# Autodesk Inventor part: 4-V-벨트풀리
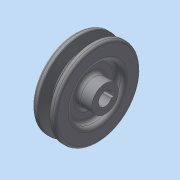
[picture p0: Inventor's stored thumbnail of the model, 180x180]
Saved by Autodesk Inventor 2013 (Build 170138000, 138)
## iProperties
Created: 2015-02
Part Number: 4-V-벨트풀리
Material: 일반
Document SubType Name: Modeling
Designer: Administrator
Density: 1 g/cm^3
Author: Administrator
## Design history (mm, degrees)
sketch "스케치1"
  geometry: L1 (0, 0)-(-25, 0); L2 (0, 11)-(0, 0); L3 (-6, 33.2)-(-6, 24.5); L4 (-12, 14)-(-12, 18.5); L5 (-9, 21.5)-(-9, 21.5); L6 (-22, 21.5)-(-22, 21.5); L7 (-19, 18.5)-(-19, 14); L8 (-22, 11)-(-25, 11); L9 (-25, 0)-(-25, 11); L10 (-25, 24.5)-(-25, 33.2); L11 (-20.217, 34.846)-(-17.79, 26.908); L12 (-16.834, 26.2)-(-14.166, 26.2); L13 (-13.21, 26.908)-(-10.783, 34.846); L14 (-23, 35.2)-(-20.695, 35.2); L15 (-10.305, 35.2)-(-8, 35.2); L16 (-9, 11)-(0, 11); A1 r 0.5 centre (-20.695, 34.7) between (-20.217, 34.846) and (-20.695, 35.2); A2 r 0.5 centre (-10.305, 34.7) between (-10.305, 35.2) and (-10.783, 34.846); A3 r 2 centre (-8, 33.2) between (-6, 33.2) and (-8, 35.2); A4 r 2 centre (-23, 33.2) between (-23, 35.2) and (-25, 33.2); A5 r 1 centre (-16.834, 27.2) between (-17.79, 26.908) and (-16.834, 26.2); A6 r 1 centre (-14.166, 27.2) between (-14.166, 26.2) and (-13.21, 26.908); A7 r 3 centre (-22, 24.5) between (-25, 24.5) and (-22, 21.5); A8 r 3 centre (-9, 24.5) between (-9, 21.5) and (-6, 24.5); A9 r 3 centre (-22, 18.5) between (-19, 18.5) and (-22, 21.5); A10 r 3 centre (-9, 18.5) between (-9, 21.5) and (-12, 18.5); A11 r 3 centre (-22, 14) between (-22, 11) and (-19, 14); A12 r 3 centre (-9, 14) between (-12, 14) and (-9, 11); 2 further points
  constraints: 32 end point, 24 point on circle, 24 tangent, 12 centre point, 9 perpendicular, 8 equal radius, 8 parallel, 3 collinear, 2 equal length, 2 point on line, 1 horizontal, 1 horizontal alignment
  dimensions: "d0" = 25 distance of L1.start L1.end; "d1" = 6 distance between parallel lines of L4 L3; "d2" = 6 distance between parallel lines of L10 L7; "d3" = 19 distance between parallel lines of L3 L10; "d4" = 2.7 distance from line of point (-11.5, 32.5) L15; "d5" = 6.3 distance from line of point (-11.5, 32.5) L12; "d6" = 34 deg angle of L13 L11; "d7" = 8 distance of point (-11.5, 32.5) point (-19.5, 32.5); "d8" = 43 diameter of L6 L1; "d9" = 65 diameter of point (-11.5, 32.5) L1; "d11" = 25 distance of L2.start L8.end; "d12" = 22 diameter of L16 L1; "d13" = 0.5 radius of A1; "d14" = 2 radius of A3; "d15" = 1 radius of A5; "d16" = 3 radius of A7
revolve "회전1" sketch "스케치1" stored, may be unused: angle "d17" = 90 deg
sketch "스케치2" dims "d18" = 11
  geometry: L1 (2, 3.7)-(-2, 3.7); L2 (-2, 3.7)-(-2, 7.3); L3 (-2, 7.3)-(2, 7.3); L4 (2, 7.3)-(2, 3.7); L5 (2, 3.7)-(-2, 7.3); L6 (-2, 3.7)-(2, 7.3); C1 r 11 at (0, 0) reference; 3 further points
  constraints: 12 end point, 3 midpoint, 2 parallel, 2 vertical alignment, 1 coincident, 1 horizontal, 1 perpendicular, 2 other
  dimensions: "d20" = 12.8 dimension on L3; "d21" = 4 distance of L2.end L3.end
extrude "돌출1" cut sketch "스케치2" stored distance "d22" = 10; taper "d23" = 0 deg
node "솔리드1"
